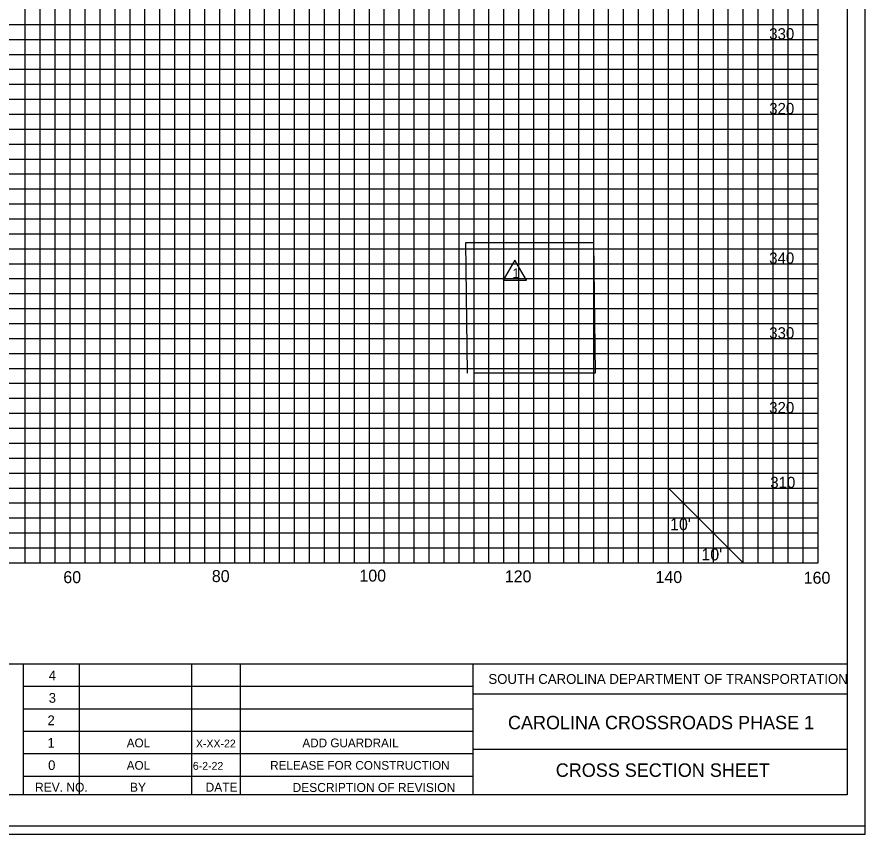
# Model space of a CAD drawing. Extents: x 967 to 1746, y 964 to 7904.
# Drawn here: x 1632.9 to 1746.3, y 1243.7 to 1353 of the extents above; entities that cross this region are included whole.
import ezdxf

# ---------------------------------------------------------------- set-up
doc = ezdxf.new("R2010")
doc.units = 0
for name, color, linetype in [('Default', 7, 'Continuous'), ('RD_SHT_Bndy', 7, 'Continuous'), ('RD_SHT_IplotShp', 7, 'Continuous'), ('RD_SHT_Misc1', 7, 'Continuous'), ('RD_SHT_MjGrid', 7, 'Continuous'), ('RD_SHT_MnGrid', 7, 'Continuous'), ('RD_SHT_TX', 7, 'Continuous'), ('RD_Sketch1', 7, 'Continuous')]:
    doc.layers.add(name, color=color, linetype=linetype)

msp = doc.modelspace()

# ---------------------------------------------------------------- linework, layer by layer
at = {"layer": 'RD_SHT_Bndy'}
for p, q in [((1743.89, 1458.46), (1743.89, 1248.98)), ((1416.11, 1266.49), (1743.89, 1266.49)), ((1633.76, 1248.94), (1633.76, 1266.49)), ((1641.26, 1248.95), (1641.26, 1266.48)), ((1656.26, 1248.95), (1656.26, 1266.48)), ((1662.76, 1248.95), (1662.76, 1266.48)), ((1693.88, 1248.98), (1693.88, 1266.49)), ((1633.76, 1263.48), (1693.88, 1263.48)), ((1743.93, 1262.43), (1693.88, 1262.43)), ((1633.76, 1260.48), (1693.88, 1260.48)), ((1633.76, 1257.48), (1693.88, 1257.48)), ((1633.76, 1254.48), (1693.88, 1254.48)), ((1743.89, 1255.04), (1693.88, 1255.04)), ((1633.76, 1251.48), (1693.88, 1251.48)), ((1743.89, 1248.98), (1416.11, 1248.98))]:
    msp.add_line(p, q, dxfattribs=at)
at = {"layer": 'RD_SHT_IplotShp'}
for points in [[(1387.41, 1243.72), (1746.28, 1243.72), (1746.28, 1463.72), (1387.41, 1463.72)], [(1408.52, 1244.84), (1746.28, 1244.84), (1746.28, 1462.6), (1408.52, 1462.6)]]:
    msp.add_lwpolyline(points, close=True, dxfattribs=at)
at = {"layer": 'RD_SHT_MjGrid'}
for p, q in [((1640, 1280), (1640, 1450)), ((1650, 1280), (1650, 1450)), ((1660, 1280), (1660, 1450)), ((1670, 1280), (1670, 1450)), ((1680, 1280), (1680, 1450)), ((1690, 1280), (1690, 1450)), ((1700, 1280), (1700, 1450)), ((1710, 1280), (1710, 1450)), ((1720, 1280), (1720, 1450)), ((1730, 1280), (1730, 1450)), ((1740, 1280), (1740, 1450)), ((1420, 1350), (1740, 1350)), ((1420, 1340), (1740, 1340)), ((1420, 1330), (1740, 1330)), ((1420, 1320), (1740, 1320)), ((1420, 1310), (1740, 1310)), ((1420, 1300), (1740, 1300)), ((1420, 1290), (1740, 1290)), ((1420, 1280), (1740, 1280))]:
    msp.add_line(p, q, dxfattribs=at)
at = {"layer": 'RD_SHT_MnGrid'}
for p, q in [((1634, 1280), (1634, 1450)), ((1636, 1280), (1636, 1450)), ((1638, 1280), (1638, 1450)), ((1642, 1280), (1642, 1450)), ((1644, 1280), (1644, 1450)), ((1646, 1280), (1646, 1450)), ((1648, 1280), (1648, 1450)), ((1652, 1280), (1652, 1450)), ((1654, 1280), (1654, 1450)), ((1656, 1280), (1656, 1450)), ((1658, 1280), (1658, 1450)), ((1662, 1280), (1662, 1450)), ((1664, 1280), (1664, 1450)), ((1666, 1280), (1666, 1450)), ((1668, 1280), (1668, 1450)), ((1672, 1280), (1672, 1450)), ((1674, 1280), (1674, 1450)), ((1676, 1280), (1676, 1450)), ((1678, 1280), (1678, 1450)), ((1682, 1280), (1682, 1450)), ((1684, 1280), (1684, 1450)), ((1686, 1280), (1686, 1450)), ((1688, 1280), (1688, 1450)), ((1692, 1280), (1692, 1450)), ((1694, 1280), (1694, 1450)), ((1696, 1280), (1696, 1450)), ((1698, 1280), (1698, 1450)), ((1702, 1280), (1702, 1450)), ((1704, 1280), (1704, 1450)), ((1706, 1280), (1706, 1450)), ((1708, 1280), (1708, 1450)), ((1712, 1280), (1712, 1450)), ((1714, 1280), (1714, 1450)), ((1716, 1280), (1716, 1450)), ((1718, 1280), (1718, 1450)), ((1722, 1280), (1722, 1450)), ((1724, 1280), (1724, 1450)), ((1726, 1280), (1726, 1450)), ((1728, 1280), (1728, 1450)), ((1732, 1280), (1732, 1450)), ((1734, 1280), (1734, 1450)), ((1736, 1280), (1736, 1450)), ((1738, 1280), (1738, 1450)), ((1420, 1352), (1740, 1352)), ((1420, 1348), (1740, 1348)), ((1420, 1346), (1740, 1346)), ((1420, 1344), (1740, 1344)), ((1420, 1342), (1740, 1342)), ((1420, 1338), (1740, 1338)), ((1420, 1336), (1740, 1336)), ((1420, 1334), (1740, 1334)), ((1420, 1332), (1740, 1332)), ((1420, 1328), (1740, 1328)), ((1420, 1326), (1740, 1326)), ((1420, 1324), (1740, 1324)), ((1420, 1322), (1740, 1322)), ((1420, 1318), (1740, 1318)), ((1420, 1316), (1740, 1316)), ((1420, 1314), (1740, 1314)), ((1420, 1312), (1740, 1312)), ((1420, 1308), (1740, 1308)), ((1420, 1306), (1740, 1306)), ((1420, 1304), (1740, 1304)), ((1420, 1302), (1740, 1302)), ((1420, 1298), (1740, 1298)), ((1420, 1296), (1740, 1296)), ((1420, 1294), (1740, 1294)), ((1420, 1292), (1740, 1292)), ((1420, 1288), (1740, 1288)), ((1420, 1286), (1740, 1286)), ((1420, 1284), (1740, 1284)), ((1420, 1282), (1740, 1282))]:
    msp.add_line(p, q, dxfattribs=at)
at = {"layer": 'RD_SHT_TX'}
for p, q in [((1692.91, 1322.85), (1709.97, 1322.85)), ((1693.12, 1305.34), (1692.91, 1322.85)), ((1709.97, 1322.85), (1710.18, 1305.34)), ((1710.18, 1305.34), (1694.04, 1305.34)), ((1720, 1290), (1730, 1280))]:
    msp.add_line(p, q, dxfattribs=at)
msp.add_lwpolyline([(1701, 1317.78), (1699.45, 1320.46), (1697.91, 1317.78)], close=True, dxfattribs=at)
at = {"layer": 'RD_Sketch1'}
msp.add_lwpolyline([(1387.41, 1243.72), (1746.28, 1243.72), (1746.28, 1463.72), (1387.41, 1463.72)], close=True, dxfattribs=at)

# ---------------------------------------------------------------- texts
at = {"layer": 'Default'}
for s, p in [('330', (1733.47, 1350)), ('320', (1733.47, 1340)), ('340', (1733.47, 1320)), ('330', (1733.47, 1310)), ('320', (1733.47, 1300)), ('310', (1733.61, 1290))]:
    msp.add_text(s, height=1.5, dxfattribs=at).set_placement(p)
at = {"layer": 'RD_SHT_Misc1'}
for s, height, p in [('AOL', 1.17, (1647.56, 1255.32)), ('X-XX-22', 1.053, (1656.81, 1255.3)), ('ADD GUARDRAIL', 1.17, (1671.05, 1255.32)), ('AOL', 1.17, (1647.56, 1252.32)), ('6-2-22', 1.053, (1656.4, 1252.31)), ('RELEASE FOR CONSTRUCTION', 1.17, (1666.74, 1252.32))]:
    msp.add_text(s, height=height, dxfattribs=at).set_placement(p)
at = {"layer": 'RD_SHT_TX'}
for s, height, p in [('1', 1.3, (1699.13, 1318.07)), ("10'", 1.6, (1720.21, 1284.36)), ("10'", 1.6, (1724.4, 1280.32)), ('60', 1.6, (1639.08, 1277.28)), ('80', 1.6, (1658.94, 1277.42)), ('100', 1.6, (1678.67, 1277.48)), ('120', 1.6, (1698.11, 1277.38)), ('140', 1.6, (1718.26, 1277.29)), ('160', 1.6, (1738.08, 1277.2)), ('4', 1.3, (1637.13, 1264.28)), ('SOUTH CAROLINA DEPARTMENT OF TRANSPORTATION', 1.32, (1695.92, 1263.8)), ('3', 1.3, (1637.13, 1261.28)), ('2', 1.3, (1636.97, 1258.28)), ('1', 1.3, (1636.97, 1255.28)), ('0', 1.3, (1637.05, 1252.28)), ('REV. NO.', 1.2, (1635.3, 1249.38)), ('BY', 1.2, (1647.99, 1249.38)), ('DATE', 1.2, (1658.1, 1249.38)), ('DESCRIPTION OF REVISION', 1.2, (1669.73, 1249.35))]:
    msp.add_text(s, height=height, dxfattribs=at).set_placement(p)
for s, p in [('CAROLINA CROSSROADS PHASE 1', (1698.54, 1257.73)), ('CROSS SECTION SHEET', (1704.93, 1251.37))]:
    msp.add_text(s, height=1.8, rotation=0, dxfattribs=at).set_placement(p)

doc.saveas('drawing.dxf')
